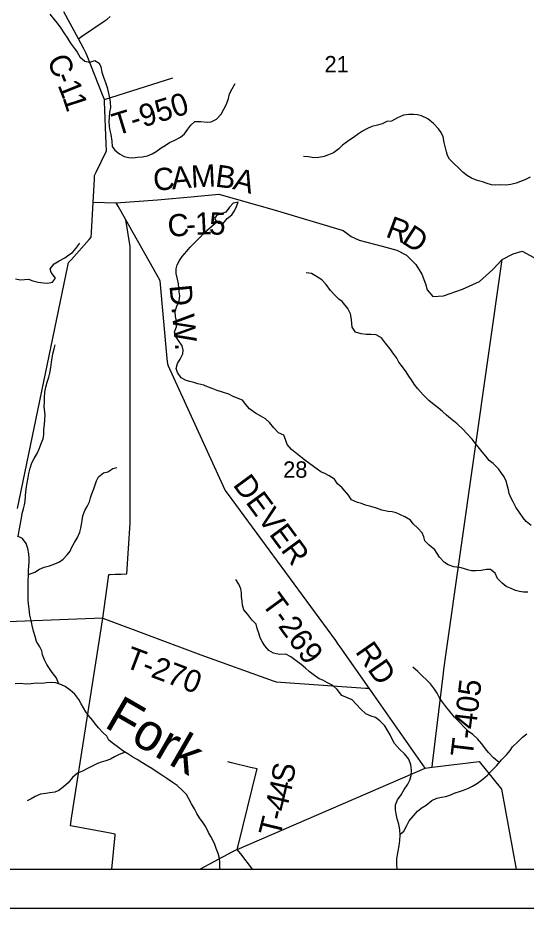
# Model space of a CAD drawing. Extents: x 0 to 34, y 0 to 22.
# Drawn here: x 6.417 to 7.716, y 14 to 16.276 of the extents above; entities that cross this region are included whole.
import ezdxf

# ---------------------------------------------------------------- set-up
doc = ezdxf.new("R2010")
doc.units = 0
for name, color, linetype in [('GM_X_County_Road', 7, 'Continuous'), ('GM_X_County_Road_Text', 7, 'Continuous'), ('GM_X_Minor_Lake', 7, 'Continuous'), ('GM_X_Minor_River', 7, 'Continuous'), ('GM_X_Minor_River_Text', 7, 'Continuous'), ('GM_X_Section_Text', 7, 'Continuous'), ('GM_X_Township_Road', 7, 'Continuous'), ('GM_X_Township_Road_Text', 7, 'Continuous'), ('SH_Data', 7, 'Continuous')]:
    doc.layers.add(name, color=color, linetype=linetype)

msp = doc.modelspace()

# ---------------------------------------------------------------- linework, layer by layer
at = {"layer": 'GM_X_County_Road'}
for points in [[(6.416, 15.0216), (6.5447, 15.6419), (6.5465, 15.6504), (6.5536, 15.6584), (6.5989, 15.7094), (6.6041, 15.7153), (6.6048, 15.7269), (6.6091, 15.8048), (6.6124, 15.8632), (6.6129, 15.8726), (6.6172, 15.8816), (6.6423, 15.9344), (6.6432, 15.9364), (6.6425, 15.9537), (6.6385, 16.0608), (6.6383, 16.0675), (6.6335, 16.0794), (6.5939, 16.179), (6.5916, 16.1848), (6.5854, 16.1965), (6.5716, 16.2223), (6.5347, 16.291)], [(6.6091, 15.8048), (6.6685, 15.8028), (6.7738, 15.8108), (6.8686, 15.8194), (6.9309, 15.8251), (7.0719, 15.785), (7.2481, 15.7319), (7.269, 15.7168), (7.2895, 15.7074), (7.3478, 15.6918), (7.386, 15.6817), (7.4107, 15.6693), (7.4342, 15.6452), (7.4495, 15.6206), (7.4587, 15.596), (7.4629, 15.5808), (7.4773, 15.5638), (7.5053, 15.5655), (7.5537, 15.582), (7.5971, 15.602), (7.6307, 15.6328), (7.6548, 15.658), (7.6834, 15.6729), (7.7057, 15.6795), (7.7361, 15.6629)], [(6.6572, 14.1), (6.6653, 14.1868), (6.6656, 14.1893), (6.6487, 14.1925), (6.5516, 14.2109), (6.5544, 14.2302), (6.6345, 14.7411), (6.3911, 14.7319), (6.3811, 14.7315)], [(6.9779, 14.1501), (7.458, 14.3583), (7.476, 14.3605), (7.5963, 14.3751), (7.6532, 14.3045), (7.6905, 14.1)], [(7.0165, 14.1), (6.9865, 14.1389), (6.9779, 14.1501), (6.9641, 14.143), (6.8827, 14.1)]]:
    msp.add_lwpolyline(points, dxfattribs=at)
at = {"layer": 'GM_X_Minor_Lake'}
for points in [[(6.9759, 15.7939), (6.9797, 15.805), (6.9669, 15.802), (6.9581, 15.7922), (6.9482, 15.779), (6.9361, 15.7745), (6.9248, 15.7707), (6.9194, 15.7617)], [(6.9194, 15.7617), (6.9285, 15.7506), (6.9421, 15.7498), (6.9516, 15.7627), (6.9641, 15.7721), (6.971, 15.7823), (6.9759, 15.7939)]]:
    msp.add_lwpolyline(points, dxfattribs=at)
at = {"layer": 'GM_X_Minor_River'}
for points in [[(6.4988, 16.2849), (6.5093, 16.2719), (6.5176, 16.2624), (6.527, 16.2495), (6.5346, 16.2377), (6.5436, 16.224), (6.5515, 16.2111), (6.562, 16.1974), (6.5681, 16.1879), (6.5756, 16.1758), (6.588, 16.1651), (6.6005, 16.1628), (6.6137, 16.1665), (6.6251, 16.1597), (6.6292, 16.1502), (6.6318, 16.1373), (6.6359, 16.124), (6.6412, 16.1103), (6.6449, 16.0982), (6.6479, 16.0864), (6.6509, 16.0716), (6.6531, 16.0602), (6.6534, 16.047), (6.6515, 16.0349), (6.6503, 16.0212), (6.6495, 16.0117), (6.6506, 15.9977), (6.6517, 15.9879), (6.6543, 15.9776), (6.6572, 15.9602), (6.6583, 15.9469), (6.6647, 15.9374), (6.6764, 15.9282), (6.6885, 15.921), (6.7002, 15.9187), (6.7108, 15.9183), (6.7229, 15.9193), (6.7347, 15.9204), (6.7479, 15.9234), (6.7604, 15.9283), (6.7706, 15.9339), (6.7835, 15.9438), (6.7938, 15.9498), (6.8048, 15.9573), (6.8165, 15.9626), (6.8324, 15.9705), (6.8431, 15.9795), (6.8514, 15.9913), (6.859, 16.0018), (6.8693, 16.0105), (6.8848, 16.0105), (6.9007, 16.0089), (6.9109, 16.01), (6.9249, 16.0167), (6.9367, 16.03), (6.9435, 16.0425), (6.95, 16.0549), (6.955, 16.0697), (6.9581, 16.0814), (6.9645, 16.0947), (6.9725, 16.1083)], [(7.7268, 15.869), (7.7127, 15.8615), (7.6904, 15.8532), (7.6772, 15.8499), (7.6651, 15.8484), (7.6507, 15.8492), (7.6379, 15.8485), (7.6277, 15.849), (7.6163, 15.8524), (7.6043, 15.8563), (7.591, 15.8601), (7.5763, 15.8659), (7.5661, 15.8716), (7.5552, 15.8808), (7.5424, 15.8937), (7.5326, 15.9029), (7.5202, 15.9143), (7.5153, 15.9238), (7.5124, 15.9336), (7.509, 15.9473), (7.5068, 15.9572), (7.5038, 15.9716), (7.4986, 15.9826), (7.4922, 15.9925), (7.4798, 16.0058), (7.4651, 16.0173), (7.4485, 16.0253), (7.4383, 16.0276), (7.4285, 16.0284), (7.416, 16.0292), (7.4024, 16.027), (7.3876, 16.0199), (7.3717, 16.0116), (7.3604, 16.0113), (7.3483, 16.0053), (7.3358, 16.0012), (7.3218, 15.9982), (7.3089, 15.9922), (7.2979, 15.9858), (7.2873, 15.979), (7.2748, 15.97), (7.2653, 15.964)], [(7.2653, 15.964), (7.2468, 15.9507)], [(7.2468, 15.9507), (7.2375, 15.9413), (7.2235, 15.9307), (7.2113, 15.9254), (7.1996, 15.9217), (7.1863, 15.9191), (7.1735, 15.9184), (7.1599, 15.9203), (7.1474, 15.9215)], [(7.2456, 15.0747), (7.2343, 15.085), (7.226, 15.0964), (7.2125, 15.1051), (7.2019, 15.1109), (7.1917, 15.1151), (7.1819, 15.1223), (7.1694, 15.1315), (7.1543, 15.1429), (7.1419, 15.1517), (7.1291, 15.1619), (7.1162, 15.1726), (7.1049, 15.1855), (7.1012, 15.1977), (7.0971, 15.2087), (7.0835, 15.2152), (7.0711, 15.2277), (7.0601, 15.2414), (7.05, 15.2506), (7.0382, 15.2574), (7.0243, 15.2654), (7.0088, 15.2765), (6.9998, 15.2879), (6.9907, 15.2989), (6.9802, 15.3031), (6.9658, 15.3085), (6.956, 15.3135), (6.9401, 15.3192), (6.9265, 15.3231), (6.9137, 15.328), (6.902, 15.333), (6.8921, 15.3372), (6.8766, 15.3403), (6.8668, 15.3438), (6.8566, 15.3464), (6.8468, 15.3491), (6.8347, 15.356), (6.8249, 15.3697), (6.8216, 15.3796), (6.825, 15.3924), (6.8322, 15.4034), (6.8387, 15.417), (6.8395, 15.4265), (6.8369, 15.4371), (6.8271, 15.4512), (6.8207, 15.4611), (6.817, 15.4732), (6.8223, 15.4861), (6.8235, 15.4982), (6.8202, 15.5122), (6.8187, 15.5251), (6.8233, 15.5391), (6.8294, 15.5528), (6.8306, 15.5656), (6.8295, 15.5751), (6.828, 15.5861), (6.8273, 15.596), (6.8247, 15.6077), (6.8213, 15.6222), (6.8214, 15.6343), (6.824, 15.6441), (6.8301, 15.6559), (6.837, 15.6661), (6.8488, 15.6793), (6.8571, 15.6895), (6.87, 15.7023), (6.8822, 15.7148), (6.8928, 15.7265), (6.9069, 15.7382), (6.9255, 15.7543)], [(6.4108, 15.609), (6.4233, 15.6063), (6.4339, 15.6066), (6.4437, 15.6077), (6.4554, 15.6039), (6.4687, 15.6), (6.4826, 15.5981), (6.4929, 15.598), (6.5054, 15.5999), (6.5133, 15.6105), (6.5017, 15.6249), (6.4998, 15.6344), (6.5101, 15.6469), (6.5226, 15.6544), (6.5366, 15.6627), (6.5468, 15.6702), (6.5563, 15.6762), (6.5654, 15.6864), (6.5757, 15.7001)], [(7.2462, 15.5504), (7.2376, 15.5565), (7.2278, 15.566), (7.2161, 15.5793), (7.2052, 15.5945), (7.1943, 15.6059), (7.1807, 15.6147), (7.1671, 15.622), (7.1539, 15.6243)], [(7.7293, 14.9785), (7.7161, 14.9881), (7.7082, 14.9976), (7.6992, 15.0117), (7.6895, 15.0253), (7.6827, 15.0383), (7.6775, 15.0478), (7.673, 15.0599), (7.6708, 15.0694), (7.6689, 15.0789), (7.6648, 15.0918), (7.6596, 15.1028), (7.6528, 15.1123), (7.6457, 15.123), (7.6321, 15.1367), (7.6216, 15.1447), (7.6133, 15.1553), (7.6039, 15.1667), (7.5934, 15.1789), (7.5859, 15.1888), (7.578, 15.1987), (7.5641, 15.2139), (7.555, 15.2238), (7.5396, 15.2383), (7.523, 15.2516), (7.5129, 15.26), (7.5023, 15.2699), (7.491, 15.2791), (7.4808, 15.2867), (7.4677, 15.2981), (7.4526, 15.3122), (7.4391, 15.3278), (7.4297, 15.3396), (7.4233, 15.3503), (7.4162, 15.3602), (7.4094, 15.3708), (7.4004, 15.3837), (7.391, 15.3959), (7.3854, 15.4062), (7.3782, 15.4161), (7.3677, 15.4305), (7.3568, 15.4446), (7.3463, 15.4583), (7.3331, 15.4652), (7.3191, 15.4664), (7.3074, 15.4668), (7.2942, 15.4684), (7.2802, 15.4722), (7.2716, 15.4848), (7.2705, 15.4943), (7.2701, 15.5049), (7.2672, 15.5193), (7.2604, 15.533), (7.2462, 15.5504)], [(6.4175, 14.9503), (6.4205, 14.9653), (6.4259, 14.9971), (6.4283, 15.0085), (6.4313, 15.021), (6.4336, 15.0312), (6.4352, 15.0407), (6.4364, 15.0532), (6.4375, 15.0645), (6.4391, 15.0774), (6.441, 15.0873), (6.443, 15.1005), (6.4453, 15.1111), (6.4484, 15.1244), (6.453, 15.1388), (6.4587, 15.1494), (6.4663, 15.1622), (6.4724, 15.1755), (6.4762, 15.1876), (6.4812, 15.2001), (6.4831, 15.211), (6.4835, 15.2239), (6.4847, 15.2364), (6.4855, 15.2493), (6.4863, 15.2592), (6.4856, 15.269), (6.4845, 15.2819), (6.4846, 15.2944), (6.4853, 15.3054), (6.4862, 15.3187), (6.4888, 15.3316), (6.4919, 15.3444), (6.4961, 15.3577), (6.4988, 15.3675), (6.5015, 15.3823), (6.5027, 15.3959), (6.5043, 15.4066), (6.5062, 15.4168), (6.5096, 15.43), (6.5123, 15.4399)], [(6.444, 14.853), (6.4602, 14.8586), (6.472, 14.8669), (6.4845, 14.8714), (6.4978, 14.8752), (6.5114, 14.88), (6.5231, 14.8857), (6.533, 14.8921), (6.5429, 14.903), (6.5509, 14.9129), (6.5551, 14.9227), (6.5615, 14.9348), (6.5695, 14.9473), (6.5752, 14.9609), (6.5779, 14.9715), (6.5795, 14.981), (6.581, 14.9908), (6.5833, 15.0033), (6.5883, 15.0169), (6.594, 15.0272), (6.5997, 15.0389), (6.6024, 15.0491), (6.6062, 15.0593), (6.6112, 15.0718), (6.6143, 15.082), (6.6177, 15.0926), (6.6234, 15.1025), (6.6356, 15.1127), (6.6469, 15.1157), (6.6598, 15.1236), (6.6697, 15.1266)], [(7.7207, 14.808), (7.7097, 14.8081), (7.6995, 14.8092), (7.6889, 14.8123), (7.678, 14.8169), (7.6652, 14.8227), (7.655, 14.8311), (7.6433, 14.8429), (7.6366, 14.8561), (7.6249, 14.8661), (7.6147, 14.8661), (7.6011, 14.8631), (7.5879, 14.8621), (7.5769, 14.8621), (7.5659, 14.8648), (7.5561, 14.8686), (7.5463, 14.8706), (7.5312, 14.8722), (7.5172, 14.8779), (7.5074, 14.884), (7.4943, 14.897), (7.489, 14.9065), (7.483, 14.916), (7.4687, 14.9278), (7.457, 14.9392), (7.4544, 14.9495), (7.4503, 14.9597), (7.4394, 14.9715), (7.4277, 14.9826), (7.4202, 14.9921), (7.4059, 15.0005), (7.3946, 15.0051), (7.384, 15.0104), (7.3735, 15.0135), (7.3632, 15.0136), (7.3474, 15.0178), (7.3334, 15.0224), (7.3195, 15.0266), (7.3059, 15.0301), (7.2949, 15.0343), (7.2847, 15.0374), (7.27, 15.0439), (7.2621, 15.0557), (7.2456, 15.0747)], [(6.5213, 14.5733), (6.5145, 14.5897), (6.5043, 14.6022), (6.4975, 14.6129), (6.4911, 14.6228), (6.4848, 14.6345), (6.4799, 14.6478), (6.478, 14.658), (6.4731, 14.6679), (6.4645, 14.6816), (6.4608, 14.6945), (6.457, 14.7085), (6.4533, 14.723), (6.4507, 14.7351), (6.4477, 14.7491), (6.4459, 14.7651), (6.4444, 14.7779), (6.4433, 14.7878), (6.4434, 14.8015), (6.443, 14.8132), (6.4431, 14.8382), (6.4439, 14.8485), (6.444, 14.8644), (6.4448, 14.8738), (6.4456, 14.8845), (6.4456, 14.8943), (6.4453, 14.9061), (6.4427, 14.9193), (6.4378, 14.9322), (6.4284, 14.9448), (6.4163, 14.9509)], [(7.2448, 14.5437), (7.2331, 14.5593), (7.2222, 14.5692), (7.2086, 14.5757), (7.1965, 14.5825), (7.1867, 14.5863), (7.175, 14.5951), (7.1618, 14.6046), (7.152, 14.6138), (7.1414, 14.6229), (7.1286, 14.6324), (7.1147, 14.6423), (7.1018, 14.6492), (7.0856, 14.6485), (7.0704, 14.652), (7.0584, 14.6589), (7.0486, 14.6706), (7.0414, 14.6813), (7.0365, 14.6908), (7.0339, 14.7006), (7.0283, 14.7147), (7.0264, 14.7261), (7.0151, 14.7371), (7.0046, 14.7504), (6.9948, 14.7626), (6.9914, 14.7747), (6.99, 14.7846), (6.9889, 14.7967), (6.9882, 14.8062), (6.9867, 14.816), (6.9814, 14.8282), (6.9743, 14.84)], [(7.6476, 14.3723), (7.6326, 14.3847), (7.6202, 14.3976), (7.6123, 14.4071), (7.6029, 14.42), (7.592, 14.433), (7.58, 14.4444), (7.5687, 14.452), (7.5566, 14.4635), (7.5472, 14.4737), (7.5333, 14.4882), (7.5217, 14.5019), (7.5108, 14.5156), (7.5006, 14.5293), (7.4942, 14.5392), (7.4886, 14.5494), (7.4818, 14.5601), (7.4713, 14.5734), (7.4627, 14.5829), (7.4506, 14.5936), (7.4393, 14.6054), (7.4269, 14.6157)], [(6.9341, 14.1), (6.9333, 14.1041), (6.933, 14.1174), (6.9323, 14.1272), (6.9293, 14.1398), (6.9241, 14.1527), (6.9203, 14.1629), (6.9151, 14.1735), (6.9098, 14.1834), (6.9042, 14.1937), (6.897, 14.2081), (6.8906, 14.2184), (6.8816, 14.2309), (6.8745, 14.2423), (6.8681, 14.2541), (6.8606, 14.267), (6.8527, 14.281), (6.8482, 14.2905), (6.8376, 14.3012), (6.8244, 14.3137), (6.8112, 14.3221), (6.798, 14.3313), (6.7848, 14.34), (6.7701, 14.3492), (6.7591, 14.3568), (6.7493, 14.3633), (6.7338, 14.3724), (6.7221, 14.3797), (6.7104, 14.3858), (6.698, 14.3942), (6.6848, 14.4026), (6.6742, 14.4106), (6.6614, 14.4205), (6.6497, 14.4296), (6.6441, 14.4399), (6.6339, 14.449), (6.6229, 14.4608), (6.6154, 14.4703), (6.6083, 14.4798), (6.5977, 14.4923), (6.5909, 14.5018), (6.5789, 14.522), (6.5725, 14.5338), (6.5624, 14.5474), (6.5503, 14.5577), (6.5382, 14.5669), (6.5284, 14.5711), (6.5137, 14.5757), (6.5027, 14.5765), (6.4902, 14.5758), (6.4785, 14.5747), (6.4645, 14.5751), (6.4509, 14.5736), (6.4369, 14.5729), (6.4244, 14.5741), (6.4096, 14.5738)], [(7.3869, 14.1), (7.3869, 14.1), (7.3854, 14.1114), (7.3859, 14.1262), (7.387, 14.136), (7.3893, 14.1459), (7.392, 14.1591), (7.3929, 14.1731), (7.3941, 14.1868), (7.3937, 14.2), (7.3911, 14.2145), (7.3867, 14.2281), (7.3841, 14.241), (7.3822, 14.2513), (7.3823, 14.2638), (7.3873, 14.2766), (7.3964, 14.2899), (7.4044, 14.3038), (7.4135, 14.3167), (7.4192, 14.3276), (7.4227, 14.339), (7.4235, 14.3526), (7.4213, 14.3667), (7.4161, 14.3807), (7.4055, 14.3944), (7.3924, 14.4066), (7.3796, 14.4207), (7.3747, 14.4302), (7.3683, 14.4431), (7.3548, 14.4659), (7.3424, 14.4785), (7.3315, 14.4872), (7.3198, 14.4907), (7.3062, 14.4968), (7.2934, 14.509), (7.2821, 14.5216), (7.2712, 14.5322), (7.2448, 14.5437)], [(7.394, 14.1893), (7.4039, 14.197), (7.4112, 14.211), (7.4173, 14.2231), (7.4279, 14.2363), (7.4385, 14.2476), (7.4507, 14.257), (7.4609, 14.263), (7.4749, 14.2751), (7.4878, 14.2815), (7.4995, 14.2837), (7.5105, 14.2859), (7.5211, 14.2889), (7.5344, 14.2949), (7.5457, 14.2983), (7.5563, 14.3016), (7.5688, 14.3065), (7.5787, 14.3121), (7.5919, 14.3193), (7.6052, 14.3298), (7.6177, 14.34), (7.628, 14.351), (7.6412, 14.3649), (7.6534, 14.3789), (7.6659, 14.3921), (7.6754, 14.4027), (7.6815, 14.4125), (7.6959, 14.4261), (7.7073, 14.4374), (7.7179, 14.4461)], [(6.6912, 14.3985), (6.6757, 14.3928), (6.6639, 14.3867), (6.6541, 14.3811), (6.6419, 14.377), (6.6298, 14.3736), (6.6203, 14.3702), (6.5953, 14.3567), (6.5821, 14.3503), (6.5692, 14.3454), (6.5567, 14.3341), (6.5453, 14.3201), (6.5331, 14.3095), (6.5213, 14.3005), (6.5115, 14.2967), (6.4982, 14.2945), (6.4884, 14.293), (6.4748, 14.2916), (6.4608, 14.2856), (6.4505, 14.2795), (6.4407, 14.2747)]]:
    msp.add_lwpolyline(points, dxfattribs=at)
at = {"layer": 'GM_X_Township_Road'}
for p, q in [((6.6383, 16.0675), (6.8132, 16.1221)), ((7.5121, 14.6526), (7.6548, 15.658)), ((6.6345, 14.7411), (6.8844, 14.6477))]:
    msp.add_line(p, q, dxfattribs=at)
for points in [[(6.5716, 16.2223), (6.5798, 16.2279), (6.6374, 16.267), (6.6451, 16.2722), (6.6528, 16.2795)], [(7.458, 14.3583), (7.4523, 14.3664), (7.3153, 14.562), (7.2411, 14.6679), (7.2361, 14.675), (7.2295, 14.684), (6.9527, 15.0609), (6.9471, 15.0685), (6.9427, 15.078), (6.8023, 15.3858), (6.7999, 15.391), (6.7986, 15.4051), (6.7806, 15.6033), (6.771, 15.6206), (6.6929, 15.7594), (6.6734, 15.7941), (6.6685, 15.8028)], [(6.6534, 14.8533), (6.666, 14.8537), (6.6808, 14.8542), (6.6956, 14.8547), (6.7041, 14.9842), (6.7041, 15.6917), (6.6929, 15.7594)], [(6.6345, 14.7411), (6.6476, 14.8404), (6.6493, 14.8532), (6.6534, 14.8533)], [(6.8844, 14.6477), (7.0699, 14.581), (7.0776, 14.5782), (7.0891, 14.5774), (7.3054, 14.5627), (7.3153, 14.562)], [(7.476, 14.3605), (7.4772, 14.3697), (7.505, 14.6011), (7.5061, 14.6104), (7.5121, 14.6526)], [(6.9779, 14.1501), (6.9803, 14.1598), (7.028, 14.3535), (7.0286, 14.356), (7.0118, 14.36), (6.9633, 14.3716), (6.9535, 14.3739)]]:
    msp.add_lwpolyline(points, dxfattribs=at)
at = {"layer": 'SH_Data'}
for p, q in [((2.1, 14.1), (8.9, 14.1)), ((2, 14), (9, 14))]:
    msp.add_line(p, q, dxfattribs=at)

# ---------------------------------------------------------------- texts
at = {"layer": 'GM_X_County_Road_Text'}
for s, rotation, p in [('C', 294.8316, (6.4898, 16.1673)), ('1', 291.8236, (6.5178, 16.1041)), ('-', 292.029, (6.5091, 16.1256)), ('1', 288.2276, (6.5305, 16.0724)), ('C', 4.9315, (6.765, 15.8334)), ('A', 4.9306, (6.8115, 15.8374)), ('M', 2.8454, (6.8608, 15.8417)), ('B', 352.2171, (6.9196, 15.8448)), ('A', 344.9804, (6.964, 15.8389)), ('C', 4.8022, (6.802, 15.7153)), ('1', 2.9102, (6.8712, 15.7209)), ('5', 357.1314, (6.9047, 15.7227)), ('R', 339.2626, (7.3544, 15.7172)), ('-', 4.4071, (6.8484, 15.7192)), ('D', 327.0849, (7.3952, 15.7021))]:
    msp.add_text(s, height=0.0568, rotation=rotation, dxfattribs=at).set_placement(p)
at = {"layer": 'GM_X_Minor_River_Text'}
msp.add_text('Fork', height=0.0947, rotation=330.0003, dxfattribs=at).set_placement((6.6349, 14.4645))
at = {"layer": 'GM_X_Section_Text'}
for s, p in [('21', (7.2007, 16.1365)), ('28', (7.0949, 15.1003))]:
    msp.add_text(s, height=0.04186, rotation=0, dxfattribs=at).set_placement(p)
at = {"layer": 'GM_X_Township_Road_Text'}
for s, height, rotation, p in [('T-950', 0.05682, 17.1021, (6.6685, 15.9744)), ('D.W.', 0.05682, 275.3651, (6.8042, 15.5915)), ('DEVER', 0.05682, 306.3759, (6.9649, 15.0819)), ('T-269', 0.05682, 306.1927, (7.0382, 14.7787)), ('RD', 0.05682, 304.7906, (7.2778, 14.6555)), ('T-270', 0.05682, 339.3446, (6.6872, 14.6172)), ('T-405', 0.05682, 83.1395, (7.5791, 14.3845)), ('S', 0.0568, 80.9277, (7.12, 14.3171)), ('4', 0.0568, 76.838, (7.1112, 14.2787)), ('4', 0.0568, 76.202, (7.1027, 14.244)), ('-', 0.0568, 76.1821, (7.0971, 14.2213)), ('T', 0.0568, 76.1831, (7.087, 14.18))]:
    msp.add_text(s, height=height, rotation=rotation, dxfattribs=at).set_placement(p)

doc.saveas('drawing.dxf')
